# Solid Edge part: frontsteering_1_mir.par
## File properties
Author: KULL
Template: Iso Metric Part.par
Last saved by: KULL
Revision: 2
Application: Solid Edge
Accuracy: 0,990
Username: KULL
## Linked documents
frontsteering_1.par
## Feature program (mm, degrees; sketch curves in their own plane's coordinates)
part copy "CopiedPart_1"
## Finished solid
Body 1: solid body, 239 faces, 533 edges, 296 vertices.
  Faces by surface: cylinder 104, torus 63, plane 40, blend 27, sphere 5
  Edges by curve: circle 280, line 198, ellipse 28, intersection 26, curve on surface 1
Bounding box of the edges (mm; curved faces can reach further): 28.000 x 37.345 x 39.295, from (-5, -22.1032, -19.6474) to (23, 15.242, 19.6474).
Cylindrical faces by radius (mm): R0.2 x28, R0.8 x37, R1.3 x1, R1.8 x2, R2 x4, R3 x5, R4 x12, R5 x8, R6 x3, R8 x2, R9 x2
Toroidal faces (ring radius, tube radius in mm): R1 r0.2 x2, R1 r0.8 x2, R1.2 r0.8 x2, R1.5 r0.2 x2, R1.6 r0.2 x2, R1.7 r0.4 x1, R2.2 r0.8 x4, R2.4 r0.4 x2, R3.2 r0.2 x4, R3.2 r0.8 x2, R4.2 r0.2 x12, R4.2 r0.8 x4, R4.8 r0.2 x4, R4.8 r0.8 x4, R5.2 r0.8 x4, R5.8 r0.8 x4, R8.2 r0.2 x2, R8.8 r0.2 x2, R8.8 r0.8 x2, R9.8 r0.8 x2
Spherical faces by radius (mm): R0.8 x2, R3 x1, R4 x2
Planar faces by outward normal: +x 3, +y 5, +z 2, -x 4, -y 5, -z 2, oblique 19
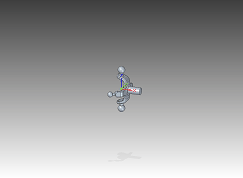
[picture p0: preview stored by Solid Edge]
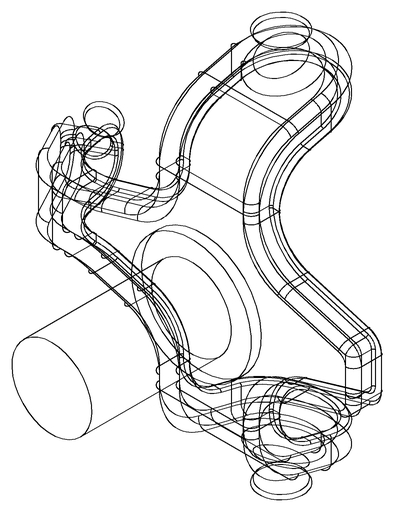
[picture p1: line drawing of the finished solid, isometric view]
